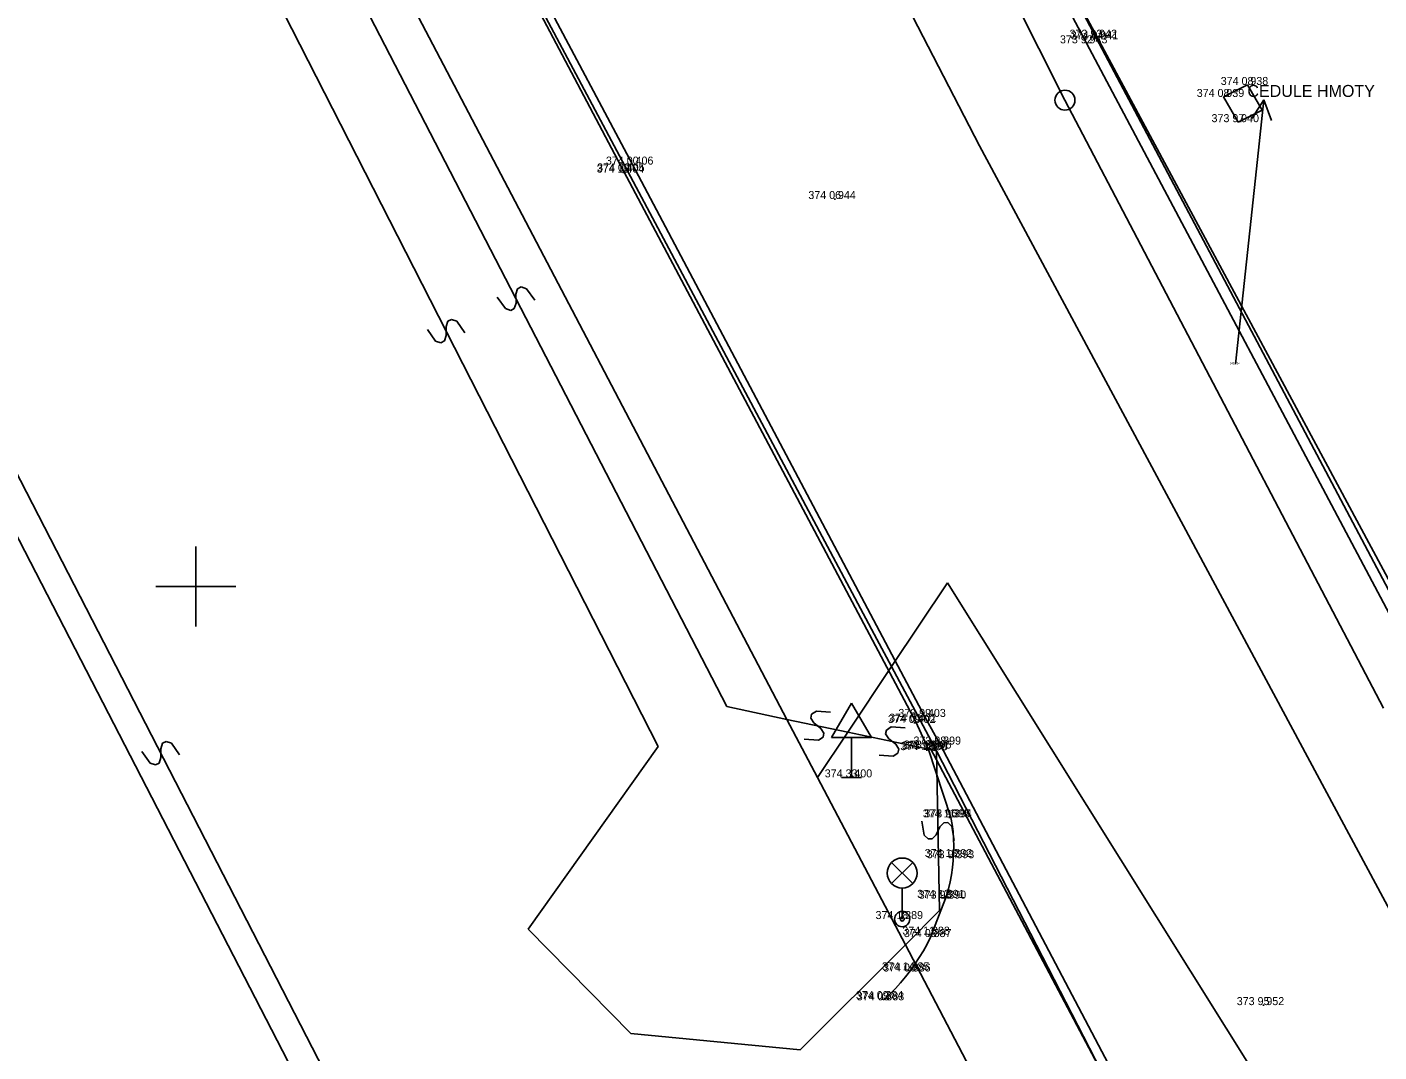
# Model space of a CAD drawing. Extents: x -601196 to -600262, y -1082523 to -1081922.
# Drawn here: x -600554.22 to -600520.42, y -1082211.63 to -1082186.02 of the extents above; entities that cross this region are included whole.
import ezdxf

# ---------------------------------------------------------------- set-up
doc = ezdxf.new("R2010")
doc.units = 0
for name, color, linetype in [('Vrstva 1', 7, 'Continuous'), ('Vrstva 10', 7, 'Continuous'), ('Vrstva 11', 7, 'Continuous'), ('Vrstva 2', 7, 'Continuous'), ('Vrstva 20', 7, 'Continuous'), ('Vrstva 3', 7, 'Continuous'), ('Vrstva 33', 7, 'Continuous'), ('Vrstva 34', 7, 'Continuous'), ('Vrstva 47', 7, 'Continuous'), ('Vrstva 61', 7, 'Continuous'), ('Vrstva 63', 7, 'Continuous')]:
    doc.layers.add(name, color=color, linetype=linetype)

msp = doc.modelspace()

# ---------------------------------------------------------------- linework, layer by layer
at = {"layer": 'Vrstva 1'}
for p, q in [((-600527.73, -1082186.43), (-600527.73, -1082186.43)), ((-600527.49, -1082186.29), (-600527.49, -1082186.29)), ((-600527.46, -1082186.33), (-600527.46, -1082186.33)), ((-600523.71, -1082187.47), (-600523.71, -1082187.47)), ((-600524.31, -1082187.77), (-600524.31, -1082187.77)), ((-600523.94, -1082188.4), (-600523.94, -1082188.4)), ((-600539.3, -1082189.63), (-600539.3, -1082189.63)), ((-600539.08, -1082189.46), (-600539.08, -1082189.46)), ((-600539.31, -1082189.66), (-600539.31, -1082189.66)), ((-600534.02, -1082190.32), (-600534.02, -1082190.32)), ((-600532.03, -1082203.41), (-600532.03, -1082203.41)), ((-600532, -1082203.38), (-600532, -1082203.38)), ((-600531.77, -1082203.26), (-600531.77, -1082203.26)), ((-600531.72, -1082204.09), (-600531.72, -1082204.09)), ((-600531.68, -1082204.07), (-600531.68, -1082204.07)), ((-600531.63, -1082204.05), (-600531.63, -1082204.05)), ((-600531.39, -1082203.95), (-600531.39, -1082203.95)), ((-600533.61, -1082204.77), (-600533.61, -1082204.77)), ((-600531.16, -1082205.77), (-600531.16, -1082205.77)), ((-600531.12, -1082205.77), (-600531.12, -1082205.77)), ((-600531.11, -1082206.76), (-600531.11, -1082206.76)), ((-600531.06, -1082206.79), (-600531.06, -1082206.79)), ((-600531.3, -1082207.78), (-600531.3, -1082207.78)), ((-600531.26, -1082207.8), (-600531.26, -1082207.8)), ((-600532.34, -1082208.31), (-600532.34, -1082208.31)), ((-600531.67, -1082208.7), (-600531.67, -1082208.7)), ((-600531.63, -1082208.76), (-600531.63, -1082208.76)), ((-600532.18, -1082209.59), (-600532.18, -1082209.59)), ((-600532.15, -1082209.62), (-600532.15, -1082209.62)), ((-600532.83, -1082210.31), (-600532.83, -1082210.31)), ((-600532.81, -1082210.34), (-600532.81, -1082210.34)), ((-600523.31, -1082210.46), (-600523.31, -1082210.46))]:
    msp.add_line(p, q, dxfattribs=at)
at = {"layer": 'Vrstva 10'}
for p, q in [((-600534.26, -1082173.54), (-600527.49, -1082186.29)), ((-600539.3, -1082189.63), (-600546.16, -1082176.67)), ((-600527.49, -1082186.29), (-600518.95, -1082202.42)), ((-600532, -1082203.38), (-600539.3, -1082189.63)), ((-600531.68, -1082204.07), (-600532, -1082203.38)), ((-600531.12, -1082205.77), (-600531.68, -1082204.07)), ((-600531.63, -1082208.76), (-600531.26, -1082207.8))]:
    msp.add_line(p, q, dxfattribs=at)
for points in [[(-600531.12, -1082205.77), (-600531.091, -1082205.947), (-600531.069, -1082206.126), (-600531.056, -1082206.305), (-600531.051, -1082206.485), (-600531.053, -1082206.665), (-600531.064, -1082206.845), (-600531.083, -1082207.024), (-600531.109, -1082207.202), (-600531.144, -1082207.378), (-600531.186, -1082207.553), (-600531.236, -1082207.726), (-600531.26, -1082207.8)], [(-600531.63, -1082208.76), (-600531.717, -1082208.935), (-600531.811, -1082209.107), (-600531.912, -1082209.274), (-600532.02, -1082209.438), (-600532.133, -1082209.598), (-600532.253, -1082209.752), (-600532.379, -1082209.903), (-600532.51, -1082210.048), (-600532.647, -1082210.187), (-600532.789, -1082210.321), (-600532.81, -1082210.34)]]:
    msp.add_lwpolyline(points, dxfattribs=at)
at = {"layer": 'Vrstva 11'}
for p, q in [((-600527.73, -1082186.43), (-600534.48, -1082173.68)), ((-600539.08, -1082189.46), (-600545.94, -1082176.53)), ((-600527.73, -1082186.43), (-600519.18, -1082202.54)), ((-600523.71, -1082187.47), (-600524.31, -1082187.77)), ((-600523.71, -1082187.47), (-600523.34, -1082188.1)), ((-600524.31, -1082187.77), (-600523.94, -1082188.4)), ((-600523.94, -1082188.4), (-600523.34, -1082188.1)), ((-600531.77, -1082203.26), (-600539.08, -1082189.46)), ((-600531.39, -1082203.95), (-600531.77, -1082203.26)), ((-600531.63, -1082204.05), (-600531.68, -1082204.07)), ((-600527.06, -1082212.68), (-600531.63, -1082204.05)), ((-600526.85, -1082212.56), (-600531.39, -1082203.95))]:
    msp.add_line(p, q, dxfattribs=at)
at = {"layer": 'Vrstva 20'}
for p, q in [((-600527.47, -1082186.33), (-600527.45, -1082186.33)), ((-600527.46, -1082186.315), (-600527.46, -1082186.33)), ((-600527.46, -1082186.345), (-600527.46, -1082186.33)), ((-600539.31, -1082189.645), (-600539.31, -1082189.66)), ((-600539.32, -1082189.66), (-600539.3, -1082189.66)), ((-600539.31, -1082189.675), (-600539.31, -1082189.66)), ((-600534.03, -1082190.32), (-600534.01, -1082190.32)), ((-600534.02, -1082190.305), (-600534.02, -1082190.32)), ((-600534.02, -1082190.335), (-600534.02, -1082190.32)), ((-600532.04, -1082203.41), (-600532.02, -1082203.41)), ((-600532.03, -1082203.395), (-600532.03, -1082203.41)), ((-600532.03, -1082203.425), (-600532.03, -1082203.41)), ((-600531.73, -1082204.09), (-600531.71, -1082204.09)), ((-600531.72, -1082204.075), (-600531.72, -1082204.09)), ((-600531.72, -1082204.105), (-600531.72, -1082204.09)), ((-600531.17, -1082205.77), (-600531.15, -1082205.77)), ((-600531.16, -1082205.755), (-600531.16, -1082205.77)), ((-600531.16, -1082205.785), (-600531.16, -1082205.77)), ((-600531.12, -1082206.76), (-600531.1, -1082206.76)), ((-600531.11, -1082206.745), (-600531.11, -1082206.76)), ((-600531.11, -1082206.775), (-600531.11, -1082206.76)), ((-600531.31, -1082207.78), (-600531.29, -1082207.78)), ((-600531.3, -1082207.765), (-600531.3, -1082207.78)), ((-600531.3, -1082207.795), (-600531.3, -1082207.78)), ((-600531.68, -1082208.7), (-600531.66, -1082208.7)), ((-600531.67, -1082208.685), (-600531.67, -1082208.7)), ((-600531.67, -1082208.715), (-600531.67, -1082208.7)), ((-600532.19, -1082209.59), (-600532.17, -1082209.59)), ((-600532.18, -1082209.575), (-600532.18, -1082209.59)), ((-600532.18, -1082209.605), (-600532.18, -1082209.59)), ((-600532.84, -1082210.31), (-600532.82, -1082210.31)), ((-600532.83, -1082210.295), (-600532.83, -1082210.31)), ((-600532.83, -1082210.325), (-600532.83, -1082210.31)), ((-600523.32, -1082210.46), (-600523.3, -1082210.46)), ((-600523.31, -1082210.445), (-600523.31, -1082210.46)), ((-600523.31, -1082210.475), (-600523.31, -1082210.46))]:
    msp.add_line(p, q, dxfattribs=at)
at = {"layer": 'Vrstva 33'}
for p, q in [((-600532.605, -1082206.895), (-600532.075, -1082207.425)), ((-600532.605, -1082207.425), (-600532.075, -1082206.895)), ((-600532.34, -1082208.31), (-600532.34, -1082207.535))]:
    msp.add_line(p, q, dxfattribs=at)
for centre, radius in [((-600532.34, -1082207.16), 0.375), ((-600532.34, -1082208.31), 0.19), ((-600532.34, -1082208.31), 0.05)]:
    msp.add_circle(centre, radius, dxfattribs=at)
at = {"layer": 'Vrstva 34'}
for p, q in [((-600534.11, -1082203.77), (-600533.61, -1082202.92)), ((-600533.61, -1082202.92), (-600533.11, -1082203.77)), ((-600534.11, -1082203.77), (-600533.11, -1082203.77)), ((-600533.61, -1082204.77), (-600533.61, -1082203.77)), ((-600533.86, -1082204.77), (-600533.36, -1082204.77))]:
    msp.add_line(p, q, dxfattribs=at)
at = {"layer": 'Vrstva 47'}
for p, q in [((-600530.41, -1082188.99), (-600548.05, -1082154.86)), ((-600528.27, -1082187.85), (-600541.81, -1082161.08)), ((-600537.63, -1082167.37), (-600519.77, -1082200.58)), ((-600532.97, -1082201.32), (-600549.06, -1082171.12)), ((-600535.22, -1082203.32), (-600547.75, -1082179.45)), ((-600536.72, -1082203), (-600547.27, -1082182.62)), ((-600538.44, -1082204), (-600549.04, -1082183.24)), ((-600552.46, -1082202.64), (-600560.53, -1082187.01)), ((-600520.31, -1082203.04), (-600528.27, -1082187.85)), ((-600523.299, -1082187.838), (-600523.601, -1082188.308)), ((-600523.46, -1082189.33), (-600523.299, -1082187.838)), ((-600523.299, -1082187.838), (-600523.104, -1082188.362)), ((-600542.72, -1082219.99), (-600559.03, -1082188.34)), ((-600517.51, -1082213.01), (-600530.41, -1082188.99)), ((-600524.01, -1082194.45), (-600523.46, -1082189.33)), ((-600541.953, -1082192.563), (-600541.996, -1082192.698)), ((-600541.996, -1082192.698), (-600541.993, -1082192.921)), ((-600541.864, -1082192.517), (-600541.953, -1082192.563)), ((-600541.73, -1082192.56), (-600541.864, -1082192.517)), ((-600541.524, -1082192.848), (-600541.73, -1082192.56)), ((-600542.259, -1082193.059), (-600542.465, -1082192.771)), ((-600541.993, -1082192.921), (-600542.036, -1082193.056)), ((-600543.697, -1082193.373), (-600543.74, -1082193.508)), ((-600543.608, -1082193.328), (-600543.697, -1082193.373)), ((-600543.473, -1082193.371), (-600543.608, -1082193.328)), ((-600543.27, -1082193.66), (-600543.473, -1082193.371)), ((-600542.125, -1082193.102), (-600542.259, -1082193.059)), ((-600542.036, -1082193.056), (-600542.125, -1082193.102)), ((-600544.006, -1082193.868), (-600544.209, -1082193.579)), ((-600543.74, -1082193.508), (-600543.739, -1082193.731)), ((-600543.871, -1082193.911), (-600544.006, -1082193.868)), ((-600543.782, -1082193.866), (-600543.871, -1082193.911)), ((-600543.739, -1082193.731), (-600543.782, -1082193.866)), ((-600532.61, -1082202), (-600531.21, -1082199.91)), ((-600531.21, -1082199.91), (-600493.08, -1082260.78)), ((-600532.61, -1082202), (-600532.97, -1082201.32)), ((-600533.7, -1082203.64), (-600532.61, -1082202)), ((-600531.48, -1082204.11), (-600532.61, -1082202)), ((-600544.98, -1082217.13), (-600552.46, -1082202.64)), ((-600535.22, -1082203.32), (-600536.72, -1082203)), ((-600534.485, -1082203.116), (-600534.604, -1082203.194)), ((-600534.132, -1082203.14), (-600534.485, -1082203.116)), ((-600533.7, -1082203.64), (-600535.22, -1082203.32)), ((-600535.22, -1082203.32), (-600534.46, -1082204.77)), ((-600534.604, -1082203.194), (-600534.624, -1082203.292)), ((-600534.624, -1082203.292), (-600534.547, -1082203.41)), ((-600534.547, -1082203.41), (-600534.372, -1082203.549)), ((-600532.615, -1082203.511), (-600532.733, -1082203.589)), ((-600532.262, -1082203.535), (-600532.615, -1082203.511)), ((-600534.434, -1082203.843), (-600534.787, -1082203.819)), ((-600534.46, -1082204.77), (-600533.7, -1082203.64)), ((-600534.315, -1082203.765), (-600534.434, -1082203.843)), ((-600534.372, -1082203.549), (-600534.295, -1082203.667)), ((-600534.295, -1082203.667), (-600534.315, -1082203.765)), ((-600531.48, -1082204.11), (-600533.7, -1082203.64)), ((-600532.733, -1082203.589), (-600532.754, -1082203.686)), ((-600532.754, -1082203.686), (-600532.677, -1082203.805)), ((-600532.677, -1082203.805), (-600532.502, -1082203.944)), ((-600551.14, -1082204.414), (-600551.345, -1082204.126)), ((-600550.833, -1082203.918), (-600550.876, -1082204.053)), ((-600550.876, -1082204.053), (-600550.873, -1082204.276)), ((-600550.744, -1082203.872), (-600550.833, -1082203.918)), ((-600550.609, -1082203.915), (-600550.744, -1082203.872)), ((-600550.404, -1082204.204), (-600550.609, -1082203.915)), ((-600538.44, -1082204), (-600541.69, -1082208.56)), ((-600532.446, -1082204.161), (-600532.564, -1082204.238)), ((-600532.502, -1082203.944), (-600532.425, -1082204.063)), ((-600532.425, -1082204.063), (-600532.446, -1082204.161)), ((-600531.41, -1082208.1), (-600531.48, -1082204.11)), ((-600522.9, -1082220.77), (-600531.48, -1082204.11)), ((-600551.005, -1082204.457), (-600551.14, -1082204.414)), ((-600550.916, -1082204.411), (-600551.005, -1082204.457)), ((-600550.873, -1082204.276), (-600550.916, -1082204.411)), ((-600532.564, -1082204.238), (-600532.917, -1082204.214)), ((-600534.46, -1082204.77), (-600532.26, -1082208.95)), ((-600531.793, -1082206.211), (-600531.849, -1082205.862)), ((-600531.691, -1082206.309), (-600531.793, -1082206.211)), ((-600531.493, -1082206.205), (-600531.591, -1082206.307)), ((-600531.396, -1082206.004), (-600531.493, -1082206.205)), ((-600531.298, -1082205.902), (-600531.396, -1082206.004)), ((-600531.198, -1082205.9), (-600531.298, -1082205.902)), ((-600531.096, -1082205.998), (-600531.198, -1082205.9)), ((-600531.04, -1082206.347), (-600531.096, -1082205.998)), ((-600531.591, -1082206.307), (-600531.691, -1082206.309)), ((-600532.26, -1082208.95), (-600531.41, -1082208.1)), ((-600541.69, -1082208.56), (-600539.12, -1082211.17)), ((-600534.89, -1082211.58), (-600532.26, -1082208.95)), ((-600527.44, -1082218.14), (-600532.26, -1082208.95)), ((-600539.12, -1082211.17), (-600534.89, -1082211.58))]:
    msp.add_line(p, q, dxfattribs=at)
for radius in [0.25, 0.005]:
    msp.add_circle((-600528.27, -1082187.85), radius, dxfattribs=at)
at = {"layer": 'Vrstva 61'}
for p, q in [((-600550, -1082199), (-600550, -1082201)), ((-600550, -1082199), (-600550, -1082201)), ((-600551, -1082200), (-600549, -1082200)), ((-600551, -1082200), (-600549, -1082200))]:
    msp.add_line(p, q, dxfattribs=at)

# ---------------------------------------------------------------- texts
at = {"layer": 'Vrstva 2'}
for s, p in [(' 943', (-600527.73, -1082186.43)), (' 942', (-600527.49, -1082186.29)), (' 941', (-600527.46, -1082186.33)), (' 938', (-600523.71, -1082187.47)), (' 939', (-600524.31, -1082187.77)), (' 940', (-600523.94, -1082188.4)), (' 406', (-600539.08, -1082189.46)), (' 404', (-600539.31, -1082189.66)), (' 405', (-600539.3, -1082189.63)), (' 944', (-600534.02, -1082190.32)), (' 403', (-600531.77, -1082203.26)), (' 402', (-600532.03, -1082203.41)), (' 401', (-600532, -1082203.38)), (' 396', (-600531.63, -1082204.05)), (' 399', (-600531.39, -1082203.95)), (' 398', (-600531.72, -1082204.09)), (' 397', (-600531.68, -1082204.07)), (' 400', (-600533.61, -1082204.77)), (' 395', (-600531.16, -1082205.77)), (' 394', (-600531.12, -1082205.77)), (' 392', (-600531.11, -1082206.76)), (' 393', (-600531.06, -1082206.79)), (' 391', (-600531.3, -1082207.78)), (' 390', (-600531.26, -1082207.8)), (' 389', (-600532.34, -1082208.31)), (' 388', (-600531.67, -1082208.7)), (' 387', (-600531.63, -1082208.76)), (' 385', (-600532.18, -1082209.59)), (' 386', (-600532.15, -1082209.62)), (' 384', (-600532.83, -1082210.31)), (' 383', (-600532.81, -1082210.34)), (' 952', (-600523.31, -1082210.46))]:
    msp.add_text(s, height=0.2, dxfattribs=at).set_placement(p)
at = {"layer": 'Vrstva 3'}
for s, p in [('373 92 ', (-600528.396, -1082186.43)), ('373 93 ', (-600528.156, -1082186.29)), ('374 04 ', (-600528.126, -1082186.33)), ('374 08 ', (-600524.376, -1082187.47)), ('374 08 ', (-600524.976, -1082187.77)), ('373 97 ', (-600524.606, -1082188.4)), ('374 00 ', (-600539.746, -1082189.46)), ('374 13 ', (-600539.976, -1082189.66)), ('374 00 ', (-600539.966, -1082189.63)), ('374 06 ', (-600534.686, -1082190.32)), ('373 99 ', (-600532.436, -1082203.26)), ('374 09 ', (-600532.696, -1082203.41)), ('374 01 ', (-600532.666, -1082203.38)), ('373 98 ', (-600532.296, -1082204.05)), ('373 98 ', (-600532.056, -1082203.95)), ('374 12 ', (-600532.386, -1082204.09)), ('373 98 ', (-600532.346, -1082204.07)), ('374 33 ', (-600534.276, -1082204.77)), ('374 11 ', (-600531.826, -1082205.77)), ('373 96 ', (-600531.786, -1082205.77)), ('374 13 ', (-600531.776, -1082206.76)), ('373 97 ', (-600531.726, -1082206.79)), ('374 12 ', (-600531.966, -1082207.78)), ('373 98 ', (-600531.926, -1082207.8)), ('374 18 ', (-600533.006, -1082208.31)), ('374 11 ', (-600532.336, -1082208.7)), ('374 03 ', (-600532.296, -1082208.76)), ('374 14 ', (-600532.846, -1082209.59)), ('374 00 ', (-600532.816, -1082209.62)), ('374 09 ', (-600533.496, -1082210.31)), ('374 03 ', (-600533.476, -1082210.34)), ('373 95 ', (-600523.976, -1082210.46))]:
    msp.add_text(s, height=0.2, dxfattribs=at).set_placement(p)
at = {"layer": 'Vrstva 47'}
msp.add_text('3412/54', height=0.05, dxfattribs=at).set_placement((-600524.149, -1082194.45))
at = {"layer": 'Vrstva 63'}
msp.add_text('CEDULE HMOTY', height=0.3, dxfattribs=at).set_placement((-600523.71, -1082187.77))

doc.saveas('drawing.dxf')
